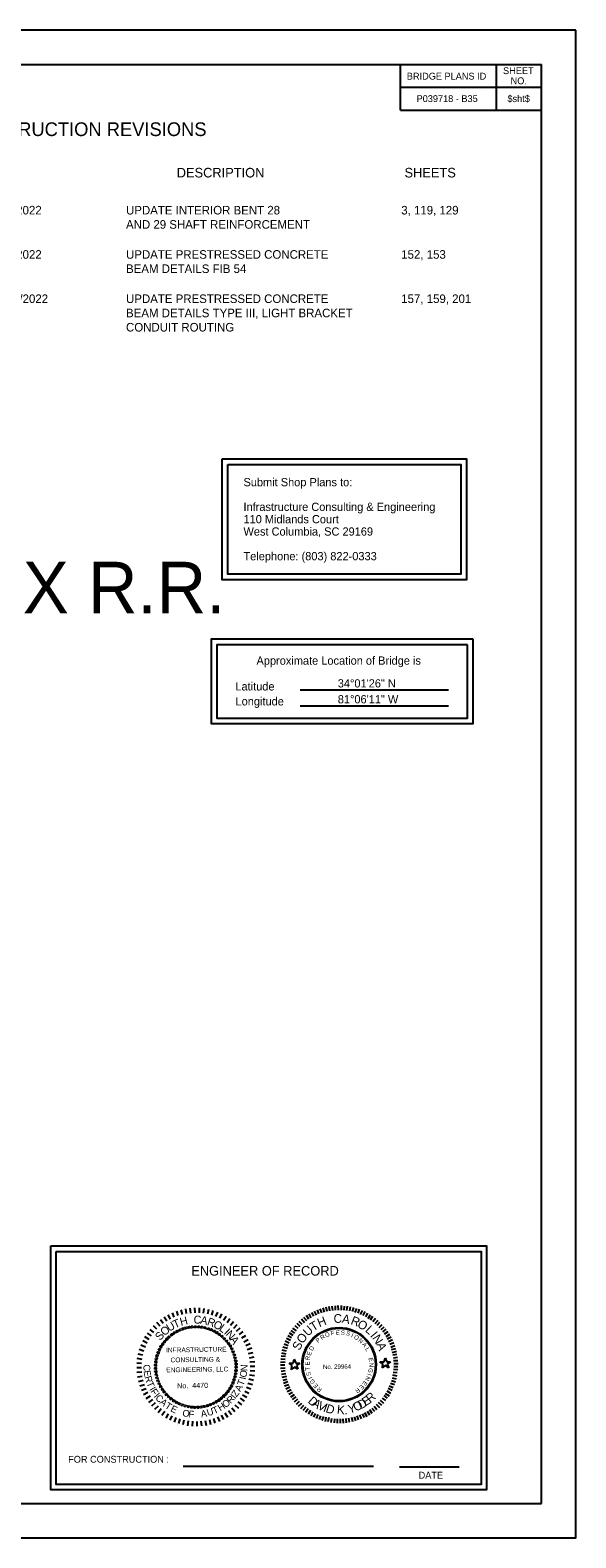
# Model space of a CAD drawing. Extents: x -1142 to 658, y -589 to 511.
# Drawn here: x 260 to 658, y -589 to 511 of the extents above; entities that cross this region are included whole.
import ezdxf

# ---------------------------------------------------------------- set-up
doc = ezdxf.new("R2010")
doc.units = 0
for name, color, linetype in [('BR_BORDER LINES', 7, 'Continuous'), ('BR_DETAILS', 7, 'Continuous'), ('BR_TEXT', 7, 'Continuous'), ('Default', 7, 'Continuous'), ('Level 31', 7, 'Continuous'), ('RD_SHT_IplotShp', 7, 'Continuous')]:
    doc.layers.add(name, color=color, linetype=linetype)

msp = doc.modelspace()

# ---------------------------------------------------------------- linework, layer by layer
at = {"layer": 'BR_BORDER LINES'}
for p, q in [((-1041.8, 485.7), (633.2, 485.7)), ((530.2, 452.3), (530.2, 485.7)), ((600.2, 452.3), (600.2, 485.7)), ((633.2, -564.3), (633.2, 485.7)), ((530.2, 469), (633.2, 469)), ((530.2, 452.3), (633.2, 452.3)), ((633.2, 427.4), (633.2, 452.3)), ((633.2, 75), (633.2, 427.5)), ((-1041.8, -564.3), (633.2, -564.3))]:
    msp.add_line(p, q, dxfattribs=at)
at = {"layer": 'BR_TEXT'}
for p, q in [((359.7, -431.2), (357.8, -428.3)), ((362.4, -429.7), (360.8, -426.6)), ((365.2, -428.3), (363.8, -425.1)), ((368.1, -427.2), (367, -423.9)), ((371.1, -426.3), (370.2, -422.9)), ((374.2, -425.7), (373.6, -422.2)), ((377.3, -425.3), (376.9, -421.7)), ((380.4, -425.1), (380.3, -421.5)), ((383.5, -425.2), (383.7, -421.6)), ((386.6, -425.5), (387.1, -422)), ((389.6, -426), (390.4, -422.6)), ((392.6, -426.8), (393.7, -423.5)), ((395.6, -427.9), (396.9, -424.6)), ((398.4, -429.1), (400, -426)), ((401.2, -430.6), (403, -427.6)), ((461.9, -431), (459.8, -428.5)), ((463.5, -429.9), (461.8, -427.2)), ((465.2, -428.7), (463.6, -425.9)), ((467, -427.7), (465.6, -424.9)), ((468.9, -426.8), (467.6, -424)), ((470.8, -425.9), (469.7, -422.9)), ((472.8, -425.2), (471.6, -422.3)), ((474.7, -424.6), (473.9, -421.5)), ((476.8, -424.1), (476, -421.1)), ((478.8, -423.7), (478.2, -420.6)), ((480.8, -423.4), (480.5, -420.3)), ((482.8, -423.2), (482.8, -420)), ((485, -423.1), (484.9, -419.9)), ((487.1, -423.2), (487.2, -419.9)), ((489.2, -423.3), (489.3, -420.2)), ((491.2, -423.5), (491.6, -420.3)), ((493.2, -423.8), (493.9, -420.8)), ((495.3, -424.3), (496.1, -421.2)), ((497.2, -424.8), (498.3, -421.9)), ((499.3, -425.5), (500.3, -422.5)), ((501.1, -426.3), (502.5, -423.4)), ((503, -427.2), (504.5, -424.3)), ((504.9, -428), (506.5, -425.3)), ((506.7, -429.2), (508.3, -426.5)), ((508.4, -430.3), (510.2, -427.7)), ((348.5, -441.9), (345.6, -439.9)), ((350.4, -439.4), (347.7, -437.2)), ((352.5, -437.1), (350, -434.7)), ((354.8, -435), (352.4, -432.3)), ((357.2, -433), (355.1, -430.2)), ((403.8, -432.3), (405.8, -429.4)), ((406.3, -434.2), (408.5, -431.5)), ((408.6, -436.3), (411, -433.7)), ((410.7, -438.5), (413.4, -436.2)), ((412.7, -440.9), (415.5, -438.8)), ((452, -441.6), (449.2, -440)), ((453.1, -440.1), (450.5, -438.1)), ((454.4, -438.3), (451.8, -436.4)), ((455.6, -436.7), (453.3, -434.6)), ((457.1, -435.1), (454.8, -432.9)), ((458.6, -433.7), (456.4, -431.4)), ((460.2, -432.4), (458.1, -429.9)), ((510.1, -431.6), (512.1, -429)), ((511.7, -432.9), (513.9, -430.5)), ((513.2, -434.2), (515.3, -432)), ((514.7, -435.8), (517, -433.6)), ((516.1, -437.4), (518.4, -435.4)), ((517.3, -439.1), (519.8, -437)), ((518.5, -440.6), (521.2, -438.9)), ((344.1, -450.1), (340.8, -448.8)), ((345.4, -447.3), (342.2, -445.7)), ((346.8, -444.5), (343.8, -442.7)), ((414.5, -443.5), (417.4, -441.6)), ((416, -446.2), (419.1, -444.5)), ((417.4, -449), (420.6, -447.6)), ((418.5, -451.9), (421.8, -450.8)), ((447.7, -451.2), (444.5, -450.1)), ((448.3, -449.2), (445.3, -448.1)), ((449.1, -447.2), (446.1, -445.9)), ((450, -445.3), (447, -443.9)), ((450.8, -443.5), (448, -441.9)), ((519.7, -442.4), (522.4, -440.8)), ((520.6, -444.2), (523.5, -442.7)), ((521.6, -446.1), (524.5, -444.7)), ((522.5, -448), (525.4, -446.9)), ((523.2, -450.1), (526.1, -448.9)), ((341.4, -462.2), (337.9, -462)), ((341.7, -459.1), (338.2, -458.6)), ((342.3, -456.1), (338.8, -455.3)), ((343.1, -453.1), (339.7, -452)), ((419.4, -454.9), (422.8, -454)), ((420, -457.9), (423.5, -457.3)), ((420.4, -461), (424, -460.7)), ((446, -461.2), (442.7, -461.3)), ((446.1, -459.2), (442.9, -458.9)), ((446.3, -457.1), (443.2, -456.7)), ((446.8, -455.2), (443.6, -454.5)), ((447.1, -453.1), (444, -452.4)), ((451.3, -463.6), (449, -461.9)), ((449, -461.9), (452, -461.9)), ((452, -461.9), (452.8, -459)), ((452.8, -459), (453.8, -461.8)), ((453.8, -461.8), (456.8, -461.8)), ((456.8, -461.8), (454.3, -463.6)), ((517.7, -462.6), (515.3, -460.9)), ((515.3, -460.9), (518.3, -460.9)), ((518.3, -460.9), (519.1, -458)), ((519.1, -458), (520.2, -460.8)), ((520.2, -460.8), (523, -460.8)), ((523, -460.8), (520.6, -462.6)), ((523.8, -451.9), (526.8, -451.1)), ((524.2, -454), (527.3, -453.2)), ((524.7, -455.9), (527.7, -455.4)), ((525.1, -458), (528.2, -457.6)), ((525.2, -460), (528.3, -460)), ((341.3, -465.3), (337.8, -465.4)), ((341.5, -468.4), (338, -468.8)), ((341.9, -471.5), (338.4, -472.1)), ((420.2, -470.3), (423.7, -470.8)), ((420.5, -467.2), (424.1, -467.5)), ((420.6, -464.1), (424.1, -464.1)), ((445.9, -463.3), (442.7, -463.4)), ((446.1, -465.5), (442.8, -465.7)), ((446.2, -467.5), (443.1, -467.9)), ((446.5, -469.6), (443.4, -470.1)), ((447, -471.6), (443.8, -472.4)), ((450.5, -466.4), (451.3, -463.6)), ((452.9, -464.7), (450.5, -466.4)), ((455.3, -466.3), (452.9, -464.7)), ((454.3, -463.6), (455.3, -466.3)), ((485.6, -462.7), (485.6, -462.7)), ((485.6, -462.7), (485.6, -462.7)), ((485.6, -462.7), (485.6, -462.7)), ((485.6, -462.7), (485.6, -462.7)), ((516.9, -465.4), (517.7, -462.6)), ((519.2, -463.6), (516.9, -465.4)), ((521.7, -465.3), (519.2, -463.6)), ((520.6, -462.6), (521.7, -465.3)), ((524.1, -472.6), (527.2, -473.3)), ((524.5, -470.4), (527.6, -471.1)), ((524.9, -468.4), (527.9, -468.8)), ((525.2, -466.3), (528.3, -466.6)), ((525.3, -464.3), (528.4, -464.3)), ((525.4, -462.1), (528.5, -462.1)), ((342.6, -474.6), (339.1, -475.4)), ((343.5, -477.6), (340.1, -478.7)), ((344.6, -480.5), (341.3, -481.9)), ((345.9, -483.3), (342.8, -484.9)), ((416.6, -482.2), (419.7, -483.7)), ((417.8, -479.3), (421.1, -480.6)), ((418.9, -476.4), (422.2, -477.4)), ((419.7, -473.4), (423.1, -474.2)), ((447.4, -473.8), (444.3, -474.5)), ((448.1, -475.6), (444.9, -476.8)), ((448.7, -477.6), (445.7, -478.7)), ((449.6, -479.5), (446.7, -480.9)), ((450.5, -481.3), (447.6, -482.9)), ((451.4, -483.2), (448.7, -484.8)), ((520.3, -482.1), (523, -483.7)), ((521.2, -480.2), (524.1, -481.7)), ((522.1, -478.4), (525, -479.7)), ((522.9, -476.5), (525.8, -477.5)), ((523.6, -474.5), (526.6, -475.5)), ((347.5, -486), (344.5, -487.9)), ((349.3, -488.5), (346.4, -490.6)), ((351.2, -490.9), (348.6, -493.3)), ((353.4, -493.2), (350.9, -495.7)), ((407.2, -494.5), (409.5, -497.1)), ((409.4, -492.3), (412, -494.8)), ((411.5, -490), (414.2, -492.3)), ((413.4, -487.5), (416.3, -489.6)), ((415.1, -484.9), (418.1, -486.7)), ((452.7, -485), (449.9, -486.7)), ((453.8, -486.5), (451.3, -488.4)), ((455.1, -488.2), (452.6, -490.3)), ((456.4, -489.9), (454.2, -492)), ((458, -491.2), (455.7, -493.6)), ((459.5, -492.7), (457.4, -495.1)), ((461.2, -494), (459.1, -496.4)), ((509.4, -494.6), (511.3, -497)), ((511, -493.2), (513.1, -495.6)), ((512.6, -491.9), (514.9, -494.2)), ((514, -490.3), (516.3, -492.6)), ((515.5, -489), (517.9, -491.1)), ((516.9, -487.3), (519.3, -489.2)), ((518.1, -485.5), (520.6, -487.4)), ((519.2, -484), (521.9, -485.6)), ((355.7, -495.3), (353.4, -498)), ((358.2, -497.2), (356.1, -500)), ((360.8, -498.8), (359, -501.9)), ((363.5, -500.3), (362, -503.5)), ((366.4, -501.6), (365.1, -504.9)), ((369.3, -502.6), (368.3, -506)), ((372.3, -503.4), (371.5, -506.9)), ((375.4, -504), (374.9, -507.5)), ((378.5, -504.3), (378.2, -507.8)), ((381.6, -504.4), (381.6, -507.9)), ((384.7, -504.2), (385, -507.7)), ((387.8, -503.8), (388.4, -507.3)), ((390.8, -503.1), (391.7, -506.6)), ((393.8, -502.2), (394.9, -505.6)), ((396.7, -501.1), (398.1, -504.4)), ((399.5, -499.8), (401.2, -502.9)), ((402.2, -498.2), (404.1, -501.2)), ((404.8, -496.4), (406.9, -499.3)), ((462.9, -495.3), (460.9, -497.8)), ((464.5, -496.4), (462.9, -499.1)), ((466.3, -497.5), (464.8, -500.3)), ((468.1, -498.5), (466.8, -501.3)), ((470, -499.3), (468.8, -502.2)), ((472, -500.2), (470.9, -503.1)), ((474, -500.7), (472.9, -503.7)), ((475.8, -501.3), (475.2, -504.4)), ((478, -501.6), (477.3, -504.8)), ((480, -502.2), (479.5, -505.2)), ((482, -502.4), (481.8, -505.5)), ((484, -502.5), (484.1, -505.6)), ((486.2, -502.6), (486.2, -505.7)), ((488.3, -502.4), (488.5, -505.6)), ((490.4, -502.2), (490.7, -505.4)), ((492.4, -502), (492.9, -505)), ((494.4, -501.4), (495.2, -504.5)), ((496.5, -501), (497.4, -504)), ((498.4, -500.4), (499.5, -503.3)), ((500.4, -499.7), (501.5, -502.6)), ((502.2, -498.8), (503.7, -501.6)), ((504.1, -497.9), (505.7, -500.7)), ((506, -496.9), (507.6, -499.6)), ((507.7, -495.7), (509.4, -498.3))]:
    msp.add_line(p, q, dxfattribs=at)
for points in [[(364.3, -439.8), (365.2, -439.3), (365.7, -440.1), (364.9, -440.7)], [(366.3, -438.6), (367.3, -438.1), (367.7, -439), (366.8, -439.5)], [(368.5, -437.5), (369.4, -437.1), (369.8, -438), (368.9, -438.4)], [(370.7, -436.6), (371.6, -436.2), (372, -437.2), (371, -437.6)], [(372.9, -435.9), (373.9, -435.6), (374.2, -436.6), (373.2, -436.9)], [(375.3, -435.3), (376.3, -435.1), (376.5, -436.2), (375.4, -436.3)], [(377.6, -434.9), (378.6, -434.8), (378.7, -435.9), (377.7, -436)], [(380, -434.8), (381, -434.8), (381, -435.8), (380, -435.8)], [(380, -434.8), (381, -434.8), (381, -435.8), (380, -435.8)], [(382.4, -434.8), (383.4, -434.9), (383.3, -435.9), (382.3, -435.8)], [(384.7, -435), (385.8, -435.1), (385.6, -436.2), (384.6, -436)], [(387.1, -435.4), (388.1, -435.6), (387.9, -436.6), (386.9, -436.4)], [(389.4, -436), (390.4, -436.3), (390.1, -437.3), (389.1, -437)], [(391.7, -436.7), (392.6, -437.1), (392.2, -438.1), (391.3, -437.7)], [(393.9, -437.7), (394.8, -438.1), (394.3, -439.1), (393.4, -438.6)], [(396, -438.8), (396.9, -439.3), (396.3, -440.2), (395.4, -439.7)], [(354.7, -450.3), (355.2, -449.3), (356.1, -449.9), (355.6, -450.8)], [(356, -448.2), (356.5, -447.4), (357.4, -447.9), (356.8, -448.8)], [(357.4, -446.3), (358, -445.5), (358.8, -446.1), (358.2, -446.9)], [(358.9, -444.5), (359.6, -443.7), (360.4, -444.4), (359.6, -445.2)], [(360.6, -442.8), (361.3, -442.1), (362, -442.8), (361.3, -443.5)], [(362.4, -441.2), (363.2, -440.6), (363.8, -441.4), (363, -442)], [(398, -440.1), (398.8, -440.7), (398.2, -441.5), (397.4, -440.9)], [(399.9, -441.5), (400.7, -442.2), (400, -442.9), (399.2, -442.3)], [(401.7, -443.1), (402.4, -443.8), (401.7, -444.5), (400.9, -443.8)], [(403.3, -444.8), (404, -445.6), (403.2, -446.2), (402.5, -445.5)], [(404.8, -446.6), (405.5, -447.5), (404.6, -448.1), (404, -447.2)], [(406.2, -448.6), (406.7, -449.5), (405.9, -450), (405.3, -449.1)], [(407.4, -450.6), (407.9, -451.5), (407, -452), (406.5, -451.1)], [(351.2, -461.5), (351.3, -460.5), (352.3, -460.6), (352.2, -461.7)], [(351.5, -459.2), (351.7, -458.2), (352.7, -458.4), (352.5, -459.4)], [(352.1, -456.9), (352.3, -455.9), (353.3, -456.2), (353, -457.2)], [(352.8, -454.6), (353.1, -453.6), (354.1, -454), (353.7, -455)], [(353.7, -452.4), (354.1, -451.4), (355, -451.9), (354.6, -452.8)], [(408.4, -452.8), (408.8, -453.7), (407.9, -454.1), (407.5, -453.2)], [(409.3, -455), (409.6, -456), (408.6, -456.3), (408.3, -455.3)], [(410, -457.3), (410.2, -458.3), (409.2, -458.5), (409, -457.5)], [(410.5, -459.6), (410.7, -460.6), (409.6, -460.8), (409.5, -459.8)], [(410.8, -462), (410.9, -463), (409.8, -463.1), (409.8, -462)], [(351, -463.9), (351.1, -462.9), (352.1, -462.9), (352, -464)], [(351, -466.3), (351, -465.3), (352, -465.2), (352.1, -466.3)], [(351.3, -468.7), (351.1, -467.6), (352.2, -467.5), (352.3, -468.6)], [(351.7, -471), (351.5, -470), (352.5, -469.8), (352.7, -470.8)], [(352.3, -473.3), (352, -472.3), (353, -472), (353.3, -473)], [(410.2, -471.4), (409.9, -472.4), (408.9, -472.2), (409.2, -471.2)], [(410.6, -469.1), (410.4, -470.1), (409.4, -469.9), (409.6, -468.9)], [(410.9, -466.7), (410.8, -467.8), (409.7, -467.7), (409.8, -466.6)], [(410.9, -464.3), (410.9, -465.4), (409.9, -465.4), (409.9, -464.3)], [(353, -475.6), (352.7, -474.6), (353.7, -474.2), (354, -475.2)], [(354, -477.8), (353.6, -476.8), (354.5, -476.4), (354.9, -477.3)], [(355.1, -479.9), (354.6, -479), (355.5, -478.5), (356, -479.4)], [(356.4, -481.9), (355.8, -481), (356.7, -480.4), (357.3, -481.3)], [(357.8, -483.8), (357.2, -483), (358, -482.3), (358.6, -483.1)], [(403.8, -484.1), (403.1, -484.9), (402.4, -484.2), (403, -483.4)], [(405.3, -482.2), (404.7, -483.1), (403.8, -482.4), (404.5, -481.6)], [(406.6, -480.2), (406.1, -481.1), (405.2, -480.6), (405.7, -479.7)], [(407.8, -478.1), (407.3, -479.1), (406.4, -478.6), (406.8, -477.7)], [(408.7, -476), (408.3, -476.9), (407.4, -476.5), (407.8, -475.6)], [(409.5, -473.7), (409.2, -474.7), (408.2, -474.4), (408.6, -473.4)], [(359.4, -485.6), (358.7, -484.8), (359.5, -484.1), (360.2, -484.8)], [(361.1, -487.2), (360.4, -486.5), (361.1, -485.7), (361.8, -486.4)], [(363, -488.7), (362.2, -488.1), (362.8, -487.2), (363.6, -487.9)], [(365, -490.1), (364.1, -489.5), (364.7, -488.6), (365.5, -489.2)], [(367, -491.2), (366.1, -490.7), (366.6, -489.8), (367.5, -490.3)], [(369.2, -492.3), (368.2, -491.8), (368.6, -490.9), (369.6, -491.3)], [(371.4, -493.1), (370.4, -492.8), (370.8, -491.8), (371.7, -492.1)], [(373.7, -493.8), (372.7, -493.5), (372.9, -492.5), (373.9, -492.8)], [(376, -494.3), (375, -494.1), (375.2, -493.1), (376.2, -493.3)], [(378.4, -494.6), (377.3, -494.5), (377.4, -493.4), (378.5, -493.5)], [(380.8, -494.7), (379.7, -494.7), (379.7, -493.6), (380.8, -493.7)], [(383.1, -494.6), (382.1, -494.7), (382, -493.6), (383.1, -493.6)], [(385.5, -494.3), (384.5, -494.5), (384.3, -493.5), (385.4, -493.3)], [(387.8, -493.9), (386.8, -494.1), (386.6, -493.1), (387.6, -492.9)], [(390.1, -493.3), (389.1, -493.6), (388.8, -492.6), (389.8, -492.3)], [(392.4, -492.4), (391.4, -492.8), (391, -491.8), (392, -491.5)], [(394.5, -491.4), (393.6, -491.9), (393.2, -491), (394.1, -490.5)], [(396.6, -490.3), (395.7, -490.8), (395.2, -489.9), (396.1, -489.4)], [(398.6, -489), (397.8, -489.6), (397.2, -488.7), (398, -488.1)], [(400.5, -487.5), (399.7, -488.1), (399, -487.3), (399.8, -486.7)], [(402.2, -485.9), (401.5, -486.6), (400.7, -485.8), (401.5, -485.1)]]:
    msp.add_lwpolyline(points, close=True, dxfattribs=at)
for radius in [27, 26.5]:
    msp.add_circle((485.5, -462.9), radius, dxfattribs=at)
at = {"layer": 'Default'}
for p, q in [((457.1, 29.3), (565.2, 29.3)), ((457.1, 17.7), (565.2, 17.7)), ((371.8, -537.1), (510.5, -537.1)), ((529.6, -537.6), (573, -537.6))]:
    msp.add_line(p, q, dxfattribs=at)
for points in [[(400.2, 197.8), (578.4, 197.8), (578.4, 109.7), (400.2, 109.7)], [(404.2, 193.8), (574.4, 193.8), (574.4, 113.7), (404.2, 113.7)], [(583.2, 66.3), (392.2, 66.3), (392.2, 4.7), (583.2, 4.7)], [(579.2, 62.3), (396.2, 62.3), (396.2, 8.7), (579.2, 8.7)], [(275.1, -376.3), (593.1, -376.3), (593.1, -554.3), (275.1, -554.3)], [(279.1, -380.3), (589.1, -380.3), (589.1, -550.3), (279.1, -550.3)]]:
    msp.add_lwpolyline(points, close=True, dxfattribs=at)
at = {"layer": 'Level 31'}
msp.add_line((658.2, 510.7), (-1141.8, 510.7), dxfattribs=at)
msp.add_lwpolyline([(-1141.8, 510.7), (-1141.8, -589.3), (658.2, -589.3), (658.2, 510.7)], dxfattribs=at)
at = {"layer": 'RD_SHT_IplotShp'}
msp.add_line((-1141.8, -589.3), (658.2, -589.3), dxfattribs=at)

# ---------------------------------------------------------------- texts
at = {"layer": 'BR_DETAILS'}
for s, p in [('BRIDGE PLANS ID', (534.9, 474.6)), ('SHEET', (605.1, 478.6)), ('NO.', (610.6, 471.2))]:
    msp.add_text(s, height=5, dxfattribs=at).set_placement(p)
at = {"layer": 'BR_TEXT'}
for s, p in [('P039718 - B35', (542, 458.2)), ('$sht$', (608.3, 458.2))]:
    msp.add_text(s, height=5, dxfattribs=at).set_placement(p)
for s, height, rotation, p in [('H', 5.82, 14.3539, (370.1, -434.7)), ('C', 5.82, 357.5781, (379.2, -432.9)), ('A', 5.82, 349.225, (383.9, -433)), ('R', 5.82, 340.5935, (388.7, -433.9)), ('H', 6.35, 21.7166, (471.1, -435.7)), ('C', 6.35, 0.9011, (481.5, -432.5)), ('A', 6.35, 349.551, (487.2, -432.3)), ('R', 6.35, 338.7873, (493.5, -433.2)), ('S', 5.82, 48.4623, (354.9, -445.8)), ('O', 5.82, 40.1092, (358, -442.3)), ('U', 5.82, 31.4777, (361.6, -439.1)), ('T', 5.82, 22.9854, (365.7, -436.6)), ('O', 5.82, 332.2404, (393.1, -435.4)), ('L', 5.82, 323.6088, (397.4, -437.6)), ('I', 5.82, 315.6734, (401, -440.1)), ('N', 5.82, 312.7498, (402.2, -441.2)), ('U', 6.35, 42.1552, (462.6, -442.7)), ('T', 6.35, 31.8521, (466.6, -438.8)), ('O', 3.18, 23.2272, (475.9, -443.2)), ('F', 3.18, 13.3346, (479.7, -441.8)), ('E', 3.18, 4.1932, (483.2, -441.1)), ('S', 3.18, 354.6763, (486.6, -441)), ('S', 3.18, 344.7836, (490.2, -441.4)), ('O', 6.34, 327.9398, (498.2, -435)), ('L', 6.35, 317.3017, (504.1, -438.3)), ('I', 6.35, 310.0142, (507.8, -442)), ('INFRASTRUCTURE', 3.492, 0.8797, (359.2, -454.1)), ('A', 5.82, 304.3967, (405.4, -444.6)), ('S', 6.34, 64.6041, (456.7, -453)), ('O', 6.35, 53.3796, (458.9, -448.1)), ('D', 3.18, 61.5455, (466, -453.2)), ('P', 3.18, 42.5116, (470.1, -447.3)), ('R', 3.18, 33.2138, (472.9, -445)), ('I', 3.18, 337.0198, (493.9, -442.8)), ('O', 3.18, 328.8803, (495.9, -443.6)), ('N', 3.18, 318.5493, (499.1, -445.7)), ('A', 3.18, 308.281, (502, -448.3)), ('L', 3.18, 298.5136, (504.3, -451.5)), ('N', 6.35, 302.0566, (509.4, -443.5)), ('A', 6.35, 290.8321, (512.6, -448.2)), ('CONSULTING &', 3.492, 0.8797, (362.5, -461.3)), ('R', 3.18, 80.3604, (463.8, -459.9)), ('E', 3.18, 89.5956, (463.9, -463.6)), ('E', 3.18, 71.1251, (464.7, -456.7)), ('E', 3.23, 280.0431, (506.9, -458.1)), ('N', 3.18, 270.4636, (507.4, -461.6)), ('C', 4.99, 272.4232, (342.6, -462.9)), ('E', 4.99, 279.5241, (342.8, -467.6)), ('R', 4.99, 286.27, (343.5, -472)), ('ENGINEERING, LLC', 3.492, 0.8797, (359.4, -468.6)), ('I', 4.99, 77.4008, (417.3, -474.2)), ('O', 4.99, 79.8861, (417.7, -472.6)), ('N', 4.99, 87.2237, (418.5, -467.8)), ('T', 3.18, 98.7995, (464.1, -467)), ('S', 3.18, 108.3791, (465.2, -470.6)), ('I', 3.18, 116.1429, (466.1, -472.6)), ('No. 29964', 3.22, 0.8797, (473.7, -466.2)), ('N', 3.18, 244.4797, (505.7, -471.1)), ('I', 3.18, 252.3062, (506.4, -469.2)), ('G', 3.18, 260.2892, (507.2, -465.3)), ('T', 4.99, 293.3709, (344.8, -476.5)), ('I', 4.99, 300.7085, (346.8, -481)), ('F', 4.99, 303.1938, (347.6, -482.5)), ('I', 4.99, 309.9396, (350, -486.2)), ('No.  4470', 3.78, 0.8797, (367.3, -480.3)), ('Z', 4.99, 55.6247, (410.7, -487)), ('A', 4.99, 62.7256, (413.4, -483.1)), ('T', 4.99, 70.0632, (415.6, -478.8)), ('G', 3.18, 124.1259, (468.2, -475.9)), ('E', 3.18, 133.862, (470.5, -478.4)), ('R', 3.18, 143.0973, (473.2, -480.8)), ('R', 3.18, 216.5236, (499.3, -479.7)), ('E', 3.18, 225.7588, (501.9, -477.3)), ('E', 3.18, 234.9001, (503.8, -474.6)), ('R', 6.32, 39.2795, (508.1, -491.1)), ('C', 4.99, 312.4249, (351, -487.5)), ('A', 4.99, 319.5258, (354.2, -491)), ('T', 4.99, 326.8634, (357.9, -494.2)), ('E', 4.99, 334.201, (362, -496.8)), ('U', 4.99, 17.3982, (389.8, -500.6)), ('T', 4.99, 24.6174, (394.4, -499.2)), ('H', 4.99, 31.955, (398.8, -497.1)), ('O', 4.99, 38.7009, (402.6, -494.8)), ('R', 4.99, 46.0385, (406.4, -491.7)), ('I', 4.99, 53.1394, (409.7, -488.3)), ('D', 6.32, 318.4862, (462.2, -490.2)), ('A', 6.31, 326.2426, (465, -492.5)), ('V', 6.32, 334.1767, (469.2, -495)), ('I', 6.31, 338.9852, (473.4, -496.9)), ('D', 6.32, 341.5046, (475.2, -497.5)), ('K.', 6.32, 355.083, (483.7, -498.7)), ('Y', 6.31, 13.9334, (492.8, -498.7)), ('O', 6.32, 24.4958, (497.4, -497.3)), ('D', 6.32, 24.4958, (501, -495.6)), ('E', 6.32, 31.8877, (504.6, -493.5)), ('O', 4.99, 348.462, (370.8, -500.4)), ('F', 4.99, 355.7996, (375.5, -501.4)), ('A', 4.99, 10.0606, (385, -501.5))]:
    msp.add_text(s, height=height, rotation=rotation, dxfattribs=at).set_placement(p)
at = {"layer": 'Default'}
for s, height, p in [('CONSTRUCTION REVISIONS', 10, (204.5, 433.4)), ('DESCRIPTION', 7, (367, 403.2)), ('SHEETS', 7, (533.2, 403.2)), ('8/23/2022', 6.25, (231.3, 376.2)), ('UPDATE INTERIOR BENT 28', 6.25, (330, 376.2)), ('3, 119, 129', 6.25, (530.8, 376.2)), ('AND 29 SHAFT REINFORCEMENT', 6.25, (330, 365.8)), ('9/28/2022', 6.25, (231.3, 343.9)), ('UPDATE PRESTRESSED CONCRETE', 6.25, (330, 343.9)), ('152, 153', 6.25, (530.8, 343.9)), ('BEAM DETAILS FIB 54', 6.25, (330, 333.5)), ('10/12/2022', 6.25, (231.3, 311.6)), ('UPDATE PRESTRESSED CONCRETE', 6.25, (330, 311.6)), ('157, 159, 201', 6.25, (530.8, 311.6)), ('CONDUIT ROUTING', 6.25, (330, 290.8)), ('BEAM DETAILS TYPE III, LIGHT BRACKET', 6.25, (330, 301.2)), ('Submit Shop Plans to:', 6, (415.7, 177.9)), ('Infrastructure Consulting & Engineering', 6, (415.7, 159.9)), ('110 Midlands Court', 6, (415.7, 150.9)), ('West Columbia, SC 29169', 6, (415.7, 141.9)), ('BRIDGE OVER SALUDA RIVER AND CSX R.R.', 37.5, (-678.7, 85.3)), ('Telephone: (803) 822-0333', 6, (415.7, 123.9)), ('Approximate Location of Bridge is', 6, (425.2, 47.7)), ('Latitude', 6, (409.8, 28.9)), ('34%%D01\'26" N', 6, (484.5, 31.1)), ('Longitude', 6, (409.9, 18)), ('81%%D06\'11" W', 6, (484.5, 19.5)), ('ENGINEER OF RECORD', 7, (377.6, -398)), ('FOR CONSTRUCTION :', 5, (287.8, -534.5)), ('DATE', 5, (543.5, -546.1))]:
    msp.add_text(s, height=height, dxfattribs=at).set_placement(p)

doc.saveas('drawing.dxf')
